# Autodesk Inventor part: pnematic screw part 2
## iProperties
Created: 2010-02
Part Number: pnematic screw part 2
Document SubType Name: Modeling
Designer: clee1
Density: 1 g/cm^3
Author: clee1
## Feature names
1. Extrusion1
2. Extrusion2
3. Extrusion3
4. Extrusion4
